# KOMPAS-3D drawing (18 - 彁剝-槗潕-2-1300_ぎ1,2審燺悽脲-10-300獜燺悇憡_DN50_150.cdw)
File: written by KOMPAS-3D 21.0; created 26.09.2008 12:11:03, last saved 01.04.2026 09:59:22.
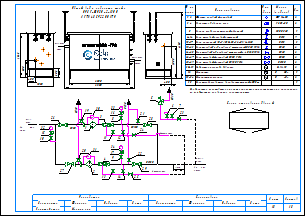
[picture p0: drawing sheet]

Sheets 1-2: A3, landscape

Document properties: Наименование: Макро:21; Автор: RaskoAdmin; Форматы листов документа: 2xA3; Полное имя файла: \\UR38nt01\Departments\КТО\КБ ПУРДГ\Заявки\Прайс-лист на типовые шкафы ГРПШ\ПРДГ_стандарт_20_03_2026\ПРДГ с РДСК\ПРДГ-ШУЭО-2-1300_до1,2МПа_Рвых-10-300кПа_РДСК_DN50_150.cdw

Title block, sheet 1: Наименование: Пункт учета газа / ПУГ-Ш-400-Р / ЛГТИ.485922.001ТУ; designation: ЛГТИ.03.4411141; sheet number: 1; Количество листов документа: 2; organisation: ООО "ЭЛЬСТЕР Газэлектроника"; Форматы листов документа: A3; stored path: C:\Рабочие документы\Компас\ПУГ\Схема.cdw; Разработал: Устинов; Проверил: Кошкин; Утвердил: Кошкин
Title block, sheet 2: sheet number: 2; stored path: D:\Рабочие документы\Заявки\ПУРДГ\ПУРДГ-ШУЭО-2-100-Р 4411220.cdw; designation, second copy: ЛГТИ.03.4411141-

Views: Вид 1, Вид 2
Referenced files: wcvoit.frw
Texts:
  Normal
  Вход
  газа
  PDI
  Выход
  Р=     кПа
  DN150
  DN50
  DN20
  Импульс DN20
  ≥5DN
  HYSWLongFangSong
  № на
  схеме
  Усл.
  обозн.
  Марка
  (модель)
  Кол.
  Фильтр газовый фланцевый
  ФГ 16-50
  Регулятор давления газа
  РДCК-50
  Клапан предохранительный сбросной
  КПС DN20
  Кран шаровой газовый латунный
  DN15
  Кран кнопочный VE-РАСКО-НЗ-1,6-G1/2-М20
  Кран шаровой "под приварку" штуцерный DN20 PN16
  Кран шаровой "под приварку" штуцерный п/п DN20 PN16
  Кран шаровой фланцевый DN50 PN16
  Кран шаровой фланцевый DN150 PN16
  Индикатор перепада давления
  Delta 15
  Манометр
  Манометр-напоромер
  Электрообогреватель взрывозащищенный 400Вт
  0...     МПа
  0...     кПа
  Общий вид и габариты шкафа
  ПРДГ-ШУЭО-2-1300
  Выход газа
  Вход газа
  Схема открывания дверей
  Р=        МПа
  logo-rasko-ge.png
  Предприятие изготовитель может заменять комплектующие на аналогичные,
  не ухудшающие заявленных характеристик.
  Должность
  Конструктор
  Фамилия
  Подпись
  Дата
  Согласовано
  Максимкин
  Лист
  Листов
  POLYLINE_STYLE_0.18_RGB_0_0_0
  POLYLINE_STYLE_0.50_RGB_0_0_0
  POLYLINE_STYLE_0.34_RGB_0_0_0
  PHANTOM_RGB_0_0_0_SC_1_THICK_0.18
  K5LT_THIN_RGB_0_0_0_THICK_0.18
  K5LT32769_RGB_0_0_0_THICK_0.18
  K5LT12_RGB_0_0_0_SC_1_THICK_0.18
  K5LT_DASHED_RGB_0_0_0_SC_1_THICK_0.18
  ACISOTGL_RGB_0_0_0_SC_0.8_THICK_0.25
  CONTINUOUS_RGB_0_127_31_THICK_0.3
  CONTINUOUS_RGB_0_0_255_THICK_0.35
  CONTINUOUS_RGB_255_0_0_THICK_0.35
  POLYLINE_STYLE_0.25_RGB_0_0_0
  CONTINUOUS_RGB_0_0_0_THICK_0.5
  POLYLINE_STYLE_0.35_RGB_0_0_255
  CONTINUOUS_RGB_0_0_0_THICK_0.4
  CONTINUOUS_RGB_0_0_0_THICK_0.35
  Без оформления
Dimensions and other numbers on the sheet: 1; 2; 3; 4; 5; 10; 27; 28; 29; 23; 8; 12; 19; 20; 21; 22; 25; 24; 30; 31; 15; 16; 26; 6; 7; 11; 14; 13; 33; 1, 2; 3, 4; 6-14; 9; 15-17; 18-23; 24-25; 26-27; 28-29; 30-31; 32; 33-34; 35; 400; 1050; 500; 305; 2500; 1565; 2800; 17; 34; 1000; 4130; 18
